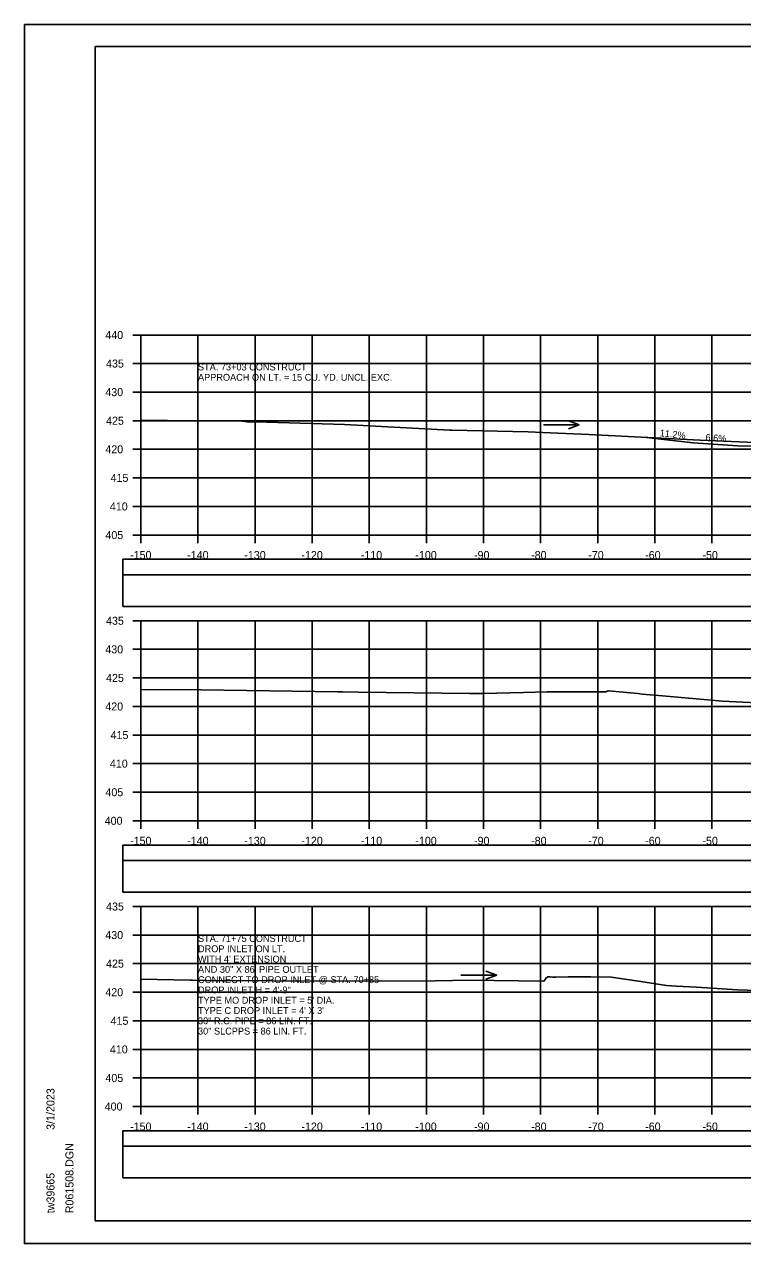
# Model space of a CAD drawing. Extents: x 1371057 to 1372761, y 380005 to 390517.
# Drawn here: x 1371390.5 to 1371516.2, y 386618.6 to 386831.9 of the extents above; entities that cross this region are included whole.
import ezdxf

# ---------------------------------------------------------------- set-up
doc = ezdxf.new("R2010")
doc.units = 0
for name, color, linetype in [('R_Axis', 7, 'Continuous'), ('R_Axis Annot', 7, 'Continuous'), ('R_Border', 7, 'Continuous'), ('R_Detour', 7, 'Continuous'), ('R_Dimension', 7, 'Continuous'), ('R_Drive', 7, 'Continuous'), ('R_Exist Surface', 7, 'Continuous'), ('R_Grid', 7, 'Continuous'), ('R_No Plot', 7, 'Continuous'), ('R_Water Annot', 7, 'Continuous'), ('R_Xsect Elev', 7, 'Continuous')]:
    doc.layers.add(name, color=color, linetype=linetype)

msp = doc.modelspace()

# ---------------------------------------------------------------- linework, layer by layer
at = {"layer": 'R_Axis'}
for p, q in [((1371409.47, 386777.54), (1371410.87, 386777.54)), ((1371410.87, 386742.54), (1371410.87, 386777.54)), ((1371409.47, 386772.54), (1371410.87, 386772.54)), ((1371409.47, 386767.54), (1371410.87, 386767.54)), ((1371409.47, 386762.54), (1371410.87, 386762.54)), ((1371409.47, 386757.54), (1371410.87, 386757.54)), ((1371409.47, 386752.54), (1371410.87, 386752.54)), ((1371409.47, 386747.54), (1371410.87, 386747.54)), ((1371409.47, 386742.54), (1371410.87, 386742.54)), ((1371410.87, 386742.54), (1371710.87, 386742.54)), ((1371410.87, 386741.14), (1371410.87, 386742.54)), ((1371420.87, 386741.14), (1371420.87, 386742.54)), ((1371430.87, 386741.14), (1371430.87, 386742.54)), ((1371440.87, 386741.14), (1371440.87, 386742.54)), ((1371450.87, 386741.14), (1371450.87, 386742.54)), ((1371460.87, 386741.14), (1371460.87, 386742.54)), ((1371470.87, 386741.14), (1371470.87, 386742.54)), ((1371480.87, 386741.14), (1371480.87, 386742.54)), ((1371490.87, 386741.14), (1371490.87, 386742.54)), ((1371500.87, 386741.14), (1371500.87, 386742.54)), ((1371510.87, 386741.14), (1371510.87, 386742.54)), ((1371409.47, 386727.54), (1371410.87, 386727.54)), ((1371410.87, 386692.54), (1371410.87, 386727.54)), ((1371409.47, 386722.54), (1371410.87, 386722.54)), ((1371409.47, 386717.54), (1371410.87, 386717.54)), ((1371409.47, 386712.54), (1371410.87, 386712.54)), ((1371409.47, 386707.54), (1371410.87, 386707.54)), ((1371409.47, 386702.54), (1371410.87, 386702.54)), ((1371409.47, 386697.54), (1371410.87, 386697.54)), ((1371409.47, 386692.54), (1371410.87, 386692.54)), ((1371410.87, 386692.54), (1371710.87, 386692.54)), ((1371410.87, 386691.14), (1371410.87, 386692.54)), ((1371420.87, 386691.14), (1371420.87, 386692.54)), ((1371430.87, 386691.14), (1371430.87, 386692.54)), ((1371440.87, 386691.14), (1371440.87, 386692.54)), ((1371450.87, 386691.14), (1371450.87, 386692.54)), ((1371460.87, 386691.14), (1371460.87, 386692.54)), ((1371470.87, 386691.14), (1371470.87, 386692.54)), ((1371480.87, 386691.14), (1371480.87, 386692.54)), ((1371490.87, 386691.14), (1371490.87, 386692.54)), ((1371500.87, 386691.14), (1371500.87, 386692.54)), ((1371510.87, 386691.14), (1371510.87, 386692.54)), ((1371409.47, 386677.54), (1371410.87, 386677.54)), ((1371410.87, 386642.54), (1371410.87, 386677.54)), ((1371409.47, 386672.54), (1371410.87, 386672.54)), ((1371409.47, 386667.54), (1371410.87, 386667.54)), ((1371409.47, 386662.54), (1371410.87, 386662.54)), ((1371409.47, 386657.54), (1371410.87, 386657.54)), ((1371409.47, 386652.54), (1371410.87, 386652.54)), ((1371409.47, 386647.54), (1371410.87, 386647.54)), ((1371409.47, 386642.54), (1371410.87, 386642.54)), ((1371410.87, 386642.54), (1371710.87, 386642.54)), ((1371410.87, 386641.14), (1371410.87, 386642.54)), ((1371420.87, 386641.14), (1371420.87, 386642.54)), ((1371430.87, 386641.14), (1371430.87, 386642.54)), ((1371440.87, 386641.14), (1371440.87, 386642.54)), ((1371450.87, 386641.14), (1371450.87, 386642.54)), ((1371460.87, 386641.14), (1371460.87, 386642.54)), ((1371470.87, 386641.14), (1371470.87, 386642.54)), ((1371480.87, 386641.14), (1371480.87, 386642.54)), ((1371490.87, 386641.14), (1371490.87, 386642.54)), ((1371500.87, 386641.14), (1371500.87, 386642.54)), ((1371510.87, 386641.14), (1371510.87, 386642.54))]:
    msp.add_line(p, q, dxfattribs=at)
at = {"layer": 'R_Border'}
for p, q in [((1371402.87, 386828), (1371719.05, 386828)), ((1371402.87, 386622.54), (1371402.87, 386828)), ((1371402.87, 386622.54), (1371402.87, 386622.54)), ((1371719.05, 386622.54), (1371402.87, 386622.54))]:
    msp.add_line(p, q, dxfattribs=at)
at = {"layer": 'R_Detour'}
for points in [[(1371407.72, 386735.58), (1371714.03, 386735.58), (1371714.03, 386738.29), (1371407.72, 386738.29)], [(1371407.72, 386685.58), (1371714.03, 386685.58), (1371714.03, 386688.29), (1371407.72, 386688.29)], [(1371407.72, 386635.58), (1371714.03, 386635.58), (1371714.03, 386638.29), (1371407.72, 386638.29)]]:
    msp.add_lwpolyline(points, close=True, dxfattribs=at)
at = {"layer": 'R_Dimension'}
for points in [[(1371407.72, 386730.06), (1371714.03, 386730.06), (1371714.03, 386735.58), (1371407.72, 386735.58)], [(1371407.72, 386680.06), (1371714.03, 386680.06), (1371714.03, 386685.58), (1371407.72, 386685.58)], [(1371407.72, 386630.06), (1371714.03, 386630.06), (1371714.03, 386635.58), (1371407.72, 386635.58)]]:
    msp.add_lwpolyline(points, close=True, dxfattribs=at)
at = {"layer": 'R_Drive'}
for p, q in [((1371498.87, 386759.65), (1371507.6, 386758.67)), ((1371515.38, 386758.16), (1371507.6, 386758.67)), ((1371527.38, 386757.92), (1371515.38, 386758.16))]:
    msp.add_line(p, q, dxfattribs=at)
at = {"layer": 'R_Exist Surface'}
for points in [[(1371410.87, 386762.66), (1371415.51, 386762.57), (1371422.28, 386762.53), (1371425.93, 386762.55), (1371426.94, 386762.55), (1371428.08, 386762.52), (1371429.46, 386762.36), (1371430.28, 386762.36), (1371432.94, 386762.29), (1371446.5, 386761.89), (1371463.88, 386760.93), (1371464.94, 386760.89), (1371465.33, 386760.89), (1371478.69, 386760.61), (1371481.18, 386760.5), (1371489.34, 386760.12), (1371508.79, 386759.16), (1371510.21, 386759.09), (1371532.04, 386758.13)], [(1371410.87, 386715.49), (1371421.38, 386715.47), (1371445.35, 386715.09), (1371445.8, 386715.09), (1371446.15, 386715.08), (1371448.95, 386715.05), (1371468.44, 386714.82), (1371470.84, 386714.81), (1371477.85, 386714.99), (1371482, 386715.09), (1371484.56, 386715.12), (1371492.37, 386715.11), (1371492.42, 386715.14), (1371492.55, 386715.22), (1371492.61, 386715.23), (1371492.78, 386715.25), (1371497.88, 386714.8), (1371498.67, 386714.72), (1371502.2, 386714.41), (1371512.72, 386713.48), (1371518.66, 386713.2)], [(1371410.87, 386664.8), (1371419.5, 386664.65), (1371419.92, 386664.65), (1371422.35, 386664.62), (1371433.89, 386664.53), (1371451.07, 386664.49), (1371452.75, 386664.51), (1371460.96, 386664.48), (1371462.4, 386664.55), (1371468.5, 386664.64), (1371481.32, 386664.48), (1371481.51, 386664.54), (1371481.89, 386665.09), (1371481.97, 386665.14), (1371482.07, 386665.2), (1371482.09, 386665.21), (1371482.23, 386665.22), (1371482.3, 386665.23), (1371482.53, 386665.24), (1371482.95, 386665.19), (1371483.51, 386665.19), (1371485.69, 386665.22), (1371489.68, 386665.21), (1371493.21, 386665.18), (1371498.41, 386664.41), (1371502.9, 386663.69), (1371504.68, 386663.62), (1371508.17, 386663.4), (1371515.34, 386662.97), (1371527.18, 386662.53)]]:
    msp.add_lwpolyline(points, dxfattribs=at)
at = {"layer": 'R_Grid'}
for p, q in [((1371410.87, 386777.54), (1371710.87, 386777.54)), ((1371410.87, 386742.54), (1371410.87, 386777.54)), ((1371420.87, 386742.54), (1371420.87, 386777.54)), ((1371430.87, 386742.54), (1371430.87, 386777.54)), ((1371440.87, 386742.54), (1371440.87, 386777.54)), ((1371450.87, 386742.54), (1371450.87, 386777.54)), ((1371460.87, 386742.54), (1371460.87, 386777.54)), ((1371470.87, 386742.54), (1371470.87, 386777.54)), ((1371480.87, 386742.54), (1371480.87, 386777.54)), ((1371490.87, 386742.54), (1371490.87, 386777.54)), ((1371500.87, 386742.54), (1371500.87, 386777.54)), ((1371510.87, 386742.54), (1371510.87, 386777.54)), ((1371410.87, 386772.54), (1371710.87, 386772.54)), ((1371410.87, 386767.54), (1371710.87, 386767.54)), ((1371410.87, 386762.54), (1371710.87, 386762.54)), ((1371410.87, 386757.54), (1371710.87, 386757.54)), ((1371410.87, 386752.54), (1371710.87, 386752.54)), ((1371410.87, 386747.54), (1371710.87, 386747.54)), ((1371410.87, 386742.54), (1371710.87, 386742.54)), ((1371410.87, 386727.54), (1371710.87, 386727.54)), ((1371410.87, 386692.54), (1371410.87, 386727.54)), ((1371420.87, 386692.54), (1371420.87, 386727.54)), ((1371430.87, 386692.54), (1371430.87, 386727.54)), ((1371440.87, 386692.54), (1371440.87, 386727.54)), ((1371450.87, 386692.54), (1371450.87, 386727.54)), ((1371460.87, 386692.54), (1371460.87, 386727.54)), ((1371470.87, 386692.54), (1371470.87, 386727.54)), ((1371480.87, 386692.54), (1371480.87, 386727.54)), ((1371490.87, 386692.54), (1371490.87, 386727.54)), ((1371500.87, 386692.54), (1371500.87, 386727.54)), ((1371510.87, 386692.54), (1371510.87, 386727.54)), ((1371410.87, 386722.54), (1371710.87, 386722.54)), ((1371410.87, 386717.54), (1371710.87, 386717.54)), ((1371410.87, 386712.54), (1371710.87, 386712.54)), ((1371410.87, 386707.54), (1371710.87, 386707.54)), ((1371410.87, 386702.54), (1371710.87, 386702.54)), ((1371410.87, 386697.54), (1371710.87, 386697.54)), ((1371410.87, 386692.54), (1371710.87, 386692.54)), ((1371410.87, 386677.54), (1371710.87, 386677.54)), ((1371410.87, 386642.54), (1371410.87, 386677.54)), ((1371420.87, 386642.54), (1371420.87, 386677.54)), ((1371430.87, 386642.54), (1371430.87, 386677.54)), ((1371440.87, 386642.54), (1371440.87, 386677.54)), ((1371450.87, 386642.54), (1371450.87, 386677.54)), ((1371460.87, 386642.54), (1371460.87, 386677.54)), ((1371470.87, 386642.54), (1371470.87, 386677.54)), ((1371480.87, 386642.54), (1371480.87, 386677.54)), ((1371490.87, 386642.54), (1371490.87, 386677.54)), ((1371500.87, 386642.54), (1371500.87, 386677.54)), ((1371510.87, 386642.54), (1371510.87, 386677.54)), ((1371410.87, 386672.54), (1371710.87, 386672.54)), ((1371410.87, 386667.54), (1371710.87, 386667.54)), ((1371410.87, 386662.54), (1371710.87, 386662.54)), ((1371410.87, 386657.54), (1371710.87, 386657.54)), ((1371410.87, 386652.54), (1371710.87, 386652.54)), ((1371410.87, 386647.54), (1371710.87, 386647.54)), ((1371410.87, 386642.54), (1371710.87, 386642.54))]:
    msp.add_line(p, q, dxfattribs=at)
at = {"layer": 'R_No Plot'}
for p, q in [((1371390.47, 386831.89), (1371723.8, 386831.89)), ((1371390.47, 386618.56), (1371723.8, 386618.56))]:
    msp.add_line(p, q, dxfattribs=at)
for points in [[(1371390.46, 386831.89), (1371723.8, 386831.89), (1371723.8, 386618.55), (1371390.46, 386618.55)], [(1371636.79, 386828), (1371656.41, 386828), (1371656.41, 386818.12), (1371672.52, 386818.12), (1371695.72, 386818.12), (1371695.84, 386789.96), (1371719.05, 386789.96), (1371719.05, 386622.54), (1371402.87, 386622.54), (1371402.87, 386828)]]:
    msp.add_lwpolyline(points, close=True, dxfattribs=at)
at = {"layer": 'R_Water Annot'}
for p, q in [((1371487.65, 386761.81), (1371485.73, 386762.51)), ((1371481.37, 386761.81), (1371487.65, 386761.81)), ((1371487.65, 386761.81), (1371485.73, 386761.11)), ((1371473.18, 386665.54), (1371471.26, 386666.24)), ((1371466.9, 386665.54), (1371473.18, 386665.54)), ((1371473.18, 386665.54), (1371471.26, 386664.84))]:
    msp.add_line(p, q, dxfattribs=at)

# ---------------------------------------------------------------- texts
at = {"layer": 'R_Axis Annot'}
for s, p in [('440', (1371404.64, 386776.84)), ('435', (1371404.77, 386771.84)), ('430', (1371404.64, 386766.84)), ('425', (1371404.77, 386761.84)), ('420', (1371404.64, 386756.84)), ('415', (1371405.56, 386751.84)), ('410', (1371405.44, 386746.84)), ('405', (1371404.66, 386741.84)), ('-150', (1371408.98, 386738.34)), ('-140', (1371418.98, 386738.34)), ('-130', (1371428.98, 386738.34)), ('-120', (1371438.98, 386738.34)), ('-110', (1371449.38, 386738.34)), ('-100', (1371458.93, 386738.34)), ('-90', (1371469.21, 386738.34)), ('-80', (1371479.21, 386738.34)), ('-70', (1371489.21, 386738.34)), ('-60', (1371499.18, 386738.34)), ('-50', (1371509.21, 386738.34)), ('435', (1371404.77, 386726.84)), ('430', (1371404.64, 386721.84)), ('425', (1371404.77, 386716.84)), ('420', (1371404.64, 386711.84)), ('415', (1371405.56, 386706.84)), ('410', (1371405.44, 386701.84)), ('405', (1371404.66, 386696.84)), ('400', (1371404.53, 386691.84)), ('-150', (1371408.98, 386688.34)), ('-140', (1371418.98, 386688.34)), ('-130', (1371428.98, 386688.34)), ('-120', (1371438.98, 386688.34)), ('-110', (1371449.38, 386688.34)), ('-100', (1371458.93, 386688.34)), ('-90', (1371469.21, 386688.34)), ('-80', (1371479.21, 386688.34)), ('-70', (1371489.21, 386688.34)), ('-60', (1371499.18, 386688.34)), ('-50', (1371509.21, 386688.34)), ('435', (1371404.77, 386676.84)), ('430', (1371404.64, 386671.84)), ('425', (1371404.77, 386666.84)), ('420', (1371404.64, 386661.84)), ('415', (1371405.56, 386656.84)), ('410', (1371405.44, 386651.84)), ('405', (1371404.66, 386646.84)), ('400', (1371404.53, 386641.84)), ('-150', (1371408.98, 386638.34)), ('-140', (1371418.98, 386638.34)), ('-130', (1371428.98, 386638.34)), ('-120', (1371438.98, 386638.34)), ('-110', (1371449.38, 386638.34)), ('-100', (1371458.93, 386638.34)), ('-90', (1371469.21, 386638.34)), ('-80', (1371479.21, 386638.34)), ('-70', (1371489.21, 386638.34)), ('-60', (1371499.18, 386638.34)), ('-50', (1371509.21, 386638.34))]:
    msp.add_text(s, height=1.4, dxfattribs=at).set_placement(p)
at = {"layer": 'R_Border'}
for s, p in [('3/1/2023', (1371395.74, 386638.46)), ('R061508.DGN', (1371399.06, 386623.86)), ('tw39665', (1371395.74, 386623.86))]:
    msp.add_text(s, height=1.4, rotation=90, dxfattribs=at).set_placement(p)
at = {"layer": 'R_Water Annot'}
for s, p in [('STA. 73+03 CONSTRUCT', (1371420.87, 386771.34)), ('APPROACH ON LT. = 15 CU. YD. UNCL. EXC.', (1371420.87, 386769.54)), ('STA. 71+75 CONSTRUCT', (1371420.87, 386671.34)), ('DROP INLET ON LT.', (1371420.87, 386669.54)), ("WITH 4' EXTENSION", (1371420.87, 386667.74)), ('AND 30" X 86\' PIPE OUTLET', (1371420.87, 386665.94)), ('CONNECT TO DROP INLET @ STA. 70+85', (1371420.87, 386664.14)), ("TYPE MO DROP INLET = 5' DIA.", (1371420.87, 386660.54)), ('DROP INLET H = 4\'-9"', (1371420.87, 386662.34)), ("TYPE C DROP INLET = 4' X 3'", (1371420.87, 386658.74)), ('30" R.C. PIPE = 86 LIN. FT.', (1371420.87, 386656.94)), ('30" SLCPPS = 86 LIN. FT. ', (1371420.87, 386655.14))]:
    msp.add_text(s, height=1.2, dxfattribs=at).set_placement(p)
at = {"layer": 'R_Xsect Elev'}
for s, rotation, p in [('11.2%', 353.6095, (1371501.68, 386759.84)), ('6.6%', 356.224, (1371509.71, 386759.04))]:
    msp.add_text(s, height=1.2, rotation=rotation, dxfattribs=at).set_placement(p)

doc.saveas('drawing.dxf')
